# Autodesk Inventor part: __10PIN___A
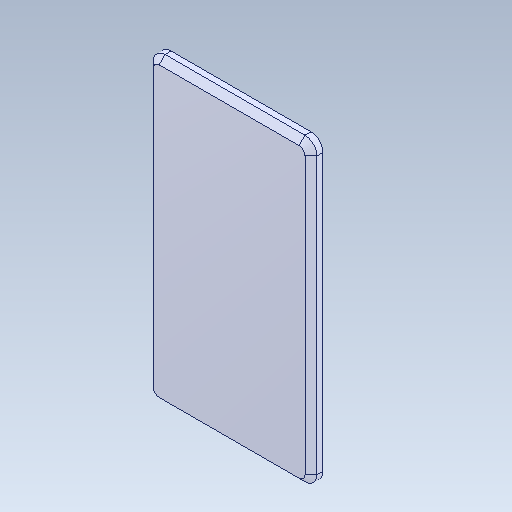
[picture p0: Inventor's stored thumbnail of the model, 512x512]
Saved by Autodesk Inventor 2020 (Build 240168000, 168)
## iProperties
Created: 2017-09
Part Number: __10PIN___A
Material: Générique
Document SubType Name: Modeling
Designer: bruno
Density: 1 g/cm^3
Appearance: Par défaut
Author: bruno
Sending System: SolidWorks 2016
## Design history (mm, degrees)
feature "Importée1"
node "Solide1"
